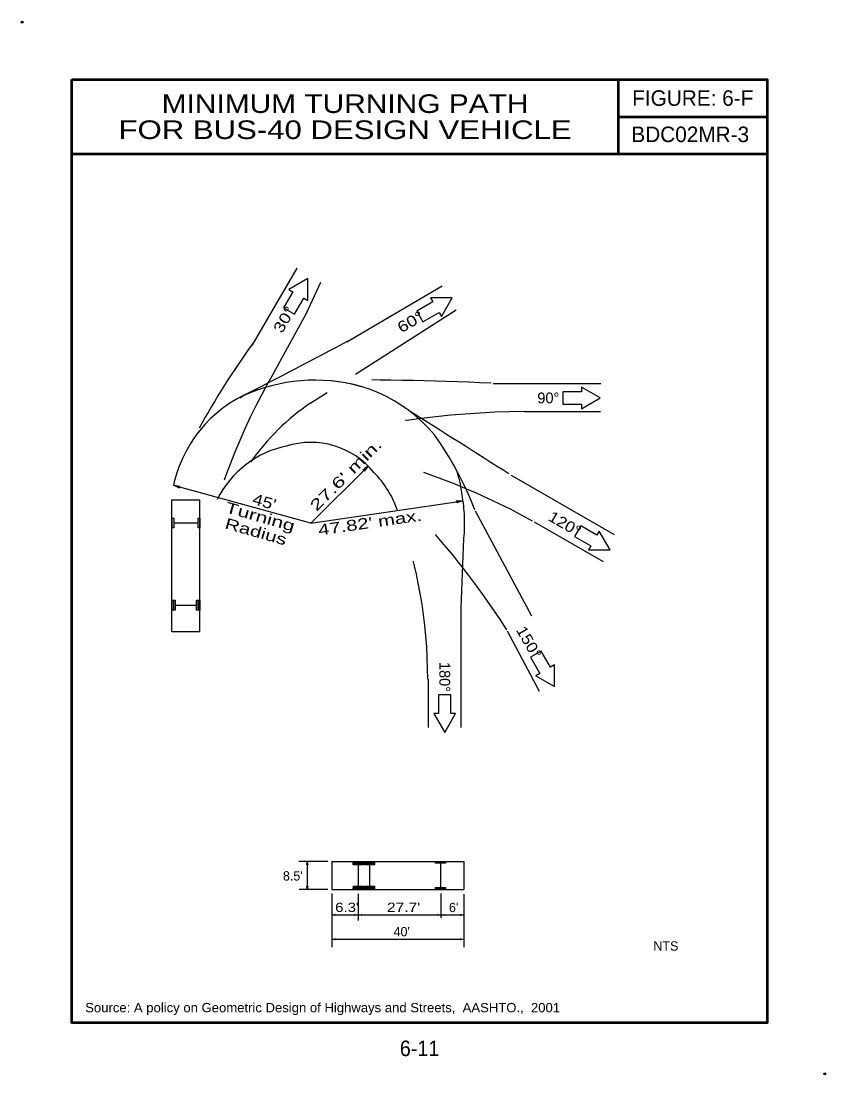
# Model space of a CAD drawing. Extents: x -3.354 to -2.679, y 4.889 to 5.773.
import ezdxf
from ezdxf.enums import TextEntityAlignment as Align

# ---------------------------------------------------------------- set-up
doc = ezdxf.new("R2010")
doc.units = 0
doc.header["$LTSCALE"] = 0.0036
doc.header["$PDMODE"] = 32
doc.header["$PDSIZE"] = 0.0018
doc.linetypes.add('LONG_DASHED', pattern=[7.5, 6, -1.5])
doc.layers.add('1', color=7, linetype='Continuous', lineweight=25)
doc.layers.add('2', color=7, linetype='Continuous', lineweight=25)

msp = doc.modelspace()

# ---------------------------------------------------------------- linework, layer by layer
at = {"layer": '1', "lineweight": 53}
for p, q in [((-2.852792, 5.724317), (-2.852792, 5.661817)), ((-2.852792, 5.693067), (-2.727792, 5.693067)), ((-3.311125, 5.661817), (-2.727792, 5.661817))]:
    msp.add_line(p, q, dxfattribs=at)
at = {"layer": '1', "linetype": 'LONG_DASHED'}
for p, q in [((-3.122458, 5.565817), (-3.160292, 5.5011)), ((-3.114492, 5.52755), (-3.102158, 5.554092)), ((-3.000542, 5.550883), (-3.080517, 5.50395)), ((-3.141508, 5.478675), (-3.114492, 5.52755)), ((-2.988808, 5.530575), (-3.097083, 5.461608)), ((-2.957633, 5.469242), (-2.867375, 5.469242)), ((-3.110725, 5.452825), (-3.097083, 5.461608)), ((-2.931367, 5.445808), (-2.867717, 5.445808)), ((-2.9427, 5.392342), (-2.854583, 5.341467)), ((-2.972808, 5.3623), (-2.897033, 5.220383)), ((-2.923267, 5.353217), (-2.865508, 5.319867)), ((-2.984625, 5.280817), (-2.98225, 5.339233)), ((-2.946117, 5.261742), (-2.919017, 5.211017))]:
    msp.add_line(p, q, dxfattribs=at)
at = {"layer": '1'}
for p, q in [((-3.062717, 5.399942), (-3.065917, 5.395575)), ((-3.225875, 5.383808), (-3.220533, 5.382908)), ((-2.983117, 5.370633), (-2.988292, 5.369033)), ((-3.225725, 5.35215), (-3.205225, 5.35215)), ((-3.22435, 5.283142), (-3.206592, 5.283142)), ((-3.09645, 5.068067), (-3.120625, 5.068067)), ((-3.11375, 5.068017), (-3.11375, 5.044675)), ((-3.113717, 5.068025), (-3.113325, 5.06535)), ((-3.070883, 5.065258), (-3.070883, 5.047492)), ((-3.061417, 5.065258), (-3.061417, 5.047492)), ((-3.001875, 5.066633), (-3.001875, 5.046133)), ((-3.09645, 5.044633), (-3.120517, 5.044633)), ((-3.113742, 5.044633), (-3.114133, 5.047308)), ((-3.093017, 5.041133), (-3.093017, 4.996242)), ((-3.070917, 5.041008), (-3.070917, 5.018617)), ((-3.001558, 5.041258), (-3.001558, 5.020933)), ((-2.982342, 5.040767), (-2.982342, 4.996242)), ((-3.092967, 5.023317), (-3.090292, 5.023717)), ((-3.092883, 5.023325), (-2.982433, 5.023325)), ((-3.071008, 5.023308), (-3.073683, 5.022908)), ((-3.070783, 5.02335), (-3.0681, 5.023742)), ((-3.001542, 5.023308), (-3.004217, 5.022908)), ((-3.001433, 5.02335), (-2.998758, 5.023742)), ((-2.982425, 5.023275), (-2.9851, 5.022883)), ((-3.093033, 5.002808), (-3.09035, 5.0032)), ((-3.093008, 5.002858), (-2.982308, 5.002858)), ((-2.982417, 5.002867), (-2.985092, 5.002475))]:
    msp.add_line(p, q, dxfattribs=at)
at = {"layer": '1', "lineweight": 53}
msp.add_lwpolyline([(-3.311125, 5.724317), (-2.727792, 5.724317), (-2.727792, 4.93265), (-3.311125, 4.93265)], close=True, dxfattribs=at)
at = {"layer": '1'}
for points in [[(-3.133492, 5.532575), (-3.124467, 5.527367), (-3.116658, 5.5409), (-3.113283, 5.538942), (-3.113267, 5.557183), (-3.129075, 5.548067), (-3.125675, 5.546108)], [(-3.02185, 5.529992), (-3.016642, 5.520975), (-3.003117, 5.528783), (-3.001167, 5.5254), (-2.992042, 5.541192), (-3.010283, 5.541192), (-3.008325, 5.537808)], [(-2.899267, 5.462275), (-2.899267, 5.451858), (-2.883642, 5.451858), (-2.883642, 5.44795), (-2.86785, 5.457067), (-2.883642, 5.466183), (-2.883642, 5.462275)], [(-3.227125, 5.347967), (-3.227125, 5.3563), (-3.225725, 5.3563), (-3.225725, 5.347967)], [(-3.205225, 5.347967), (-3.205225, 5.3563), (-3.203833, 5.3563), (-3.203833, 5.347967)], [(-2.8842, 5.349808), (-2.889408, 5.340783), (-2.875875, 5.332975), (-2.877833, 5.3296), (-2.859592, 5.329592), (-2.868708, 5.345392), (-2.870667, 5.341992)], [(-3.227158, 5.278975), (-3.227158, 5.287308), (-3.225758, 5.287308), (-3.225758, 5.278975)], [(-3.22575, 5.278975), (-3.22575, 5.287308), (-3.22435, 5.287308), (-3.22435, 5.278975)], [(-3.206592, 5.279008), (-3.206592, 5.287342), (-3.2052, 5.287342), (-3.2052, 5.279008)], [(-3.205167, 5.278975), (-3.205167, 5.287308), (-3.203767, 5.287308), (-3.203767, 5.278975)], [(-2.91735, 5.244658), (-2.926375, 5.23945), (-2.918558, 5.225925), (-2.92195, 5.223975), (-2.906158, 5.21485), (-2.906158, 5.233092), (-2.909542, 5.231133)], [(-2.993133, 5.207858), (-3.00355, 5.207858), (-3.00355, 5.192233), (-3.007458, 5.192233), (-2.998342, 5.176442), (-2.989225, 5.192233), (-2.993133, 5.192233)], [(-3.07505, 5.068058), (-3.066717, 5.068058), (-3.066717, 5.066658), (-3.07505, 5.066658)], [(-3.065583, 5.068058), (-3.05725, 5.068058), (-3.05725, 5.066658), (-3.065583, 5.066658)], [(-3.006058, 5.068025), (-2.997725, 5.068025), (-2.997725, 5.066633), (-3.006058, 5.066633)], [(-3.07505, 5.06665), (-3.066717, 5.06665), (-3.066717, 5.065258), (-3.07505, 5.065258)], [(-3.065583, 5.06665), (-3.05725, 5.06665), (-3.05725, 5.065258), (-3.065583, 5.065258)], [(-3.07505, 5.046067), (-3.066717, 5.046067), (-3.066717, 5.044675), (-3.07505, 5.044675)], [(-3.075017, 5.047492), (-3.066683, 5.047492), (-3.066683, 5.0461), (-3.075017, 5.0461)], [(-3.065583, 5.046067), (-3.05725, 5.046067), (-3.05725, 5.044675), (-3.065583, 5.044675)], [(-3.06555, 5.047492), (-3.057217, 5.047492), (-3.057217, 5.0461), (-3.06555, 5.0461)], [(-3.006058, 5.046133), (-2.997725, 5.046133), (-2.997725, 5.044733), (-3.006058, 5.044733)]]:
    msp.add_lwpolyline(points, close=True, dxfattribs=at)
for points in [[(-3.065833, 5.396775), (-3.067183, 5.396642), (-3.062667, 5.399983)], [(-3.065933, 5.395592), (-3.065825, 5.396758), (-3.065833, 5.396775)], [(-3.221642, 5.382442), (-3.220917, 5.3813), (-3.225933, 5.383842)], [(-3.220542, 5.382883), (-3.221633, 5.382467), (-3.221642, 5.382442)], [(-3.227167, 5.261008), (-3.227167, 5.371683), (-3.203725, 5.371683)], [(-3.227167, 5.261008), (-3.203725, 5.261008), (-3.203725, 5.371683)], [(-2.987508, 5.36995), (-2.988667, 5.37065), (-2.98305, 5.370633)], [(-2.9883, 5.369058), (-2.987508, 5.369933), (-2.987508, 5.36995)], [(-3.113708, 5.0658), (-3.114142, 5.065275), (-3.113708, 5.068058)], [(-3.093017, 5.068067), (-2.982342, 5.068067), (-2.982342, 5.044633)], [(-3.093017, 5.068067), (-3.093017, 5.044633), (-2.982342, 5.044633)], [(-3.113333, 5.065342), (-3.1137, 5.0658), (-3.113708, 5.0658)], [(-3.114125, 5.047317), (-3.11375, 5.046858), (-3.113742, 5.046858)], [(-3.113742, 5.046858), (-3.113308, 5.047383), (-3.113742, 5.0446)], [(-3.090742, 5.023317), (-3.090217, 5.022892), (-3.093, 5.023317)], [(-3.090283, 5.0237), (-3.090742, 5.023325), (-3.090742, 5.023317)], [(-3.073242, 5.023308), (-3.073758, 5.023733), (-3.070975, 5.023308)], [(-3.0737, 5.022925), (-3.073242, 5.0233), (-3.073242, 5.023308)], [(-3.06855, 5.02335), (-3.068033, 5.022925), (-3.070808, 5.02335)], [(-3.068092, 5.023733), (-3.06855, 5.023358), (-3.06855, 5.02335)], [(-3.003767, 5.023308), (-3.004292, 5.023733), (-3.001508, 5.023308)], [(-3.004225, 5.022925), (-3.003767, 5.0233), (-3.003767, 5.023308)], [(-2.999208, 5.02335), (-2.998683, 5.022925), (-3.001467, 5.02335)], [(-2.99875, 5.023733), (-2.999208, 5.023358), (-2.999208, 5.02335)], [(-2.984658, 5.023275), (-2.985175, 5.0237), (-2.982392, 5.023275)], [(-2.985117, 5.022892), (-2.984658, 5.023267), (-2.984658, 5.023275)], [(-3.0908, 5.002808), (-3.090283, 5.002383), (-3.093058, 5.002808)], [(-3.090342, 5.003192), (-3.0908, 5.002817), (-3.0908, 5.002808)], [(-2.984642, 5.002867), (-2.985167, 5.0033), (-2.982383, 5.002867)], [(-2.9851, 5.002483), (-2.984642, 5.002858), (-2.984642, 5.002867)]]:
    msp.add_lwpolyline(points, dxfattribs=at)
at = {"layer": '1', "linetype": 'LONG_DASHED'}
for centre, radius, start, end in [((-2.649658, 5.129911), 0.631436, 143.85184, 151.45564), ((-5.215751, 9.492155), 4.523442, 296.91573, 298.19355), ((-2.655719, 5.198735), 0.560674, 150.04704, 167.5392), ((-3.107381, 5.327415), 0.144521, 74.65813, 114.57173), ((-3.10463, 5.344889), 0.127001, 39.79656, 93.02916), ((-3.095024, 2.321509), 3.150838, 87.53498, 90.25069), ((-3.117009, 5.359497), 0.111714, 116.17598, 173.14712), ((-3.089515, 5.339567), 0.142368, 123.0881, 124.50135), ((-3.00189, 5.291288), 0.194783, 123.97021, 144.80772), ((-2.927021, 4.721892), 0.7237, 90.36182, 106.05387), ((-12.138996, -9.051551), 17.122876, 57.52224, 57.8535), ((-3.232552, 5.264489), 0.277481, 20.82313, 35.6417), ((-3.114562, 5.335272), 0.08304, 100.81496, 153.94695), ((-3.11056, 5.352056), 0.067706, 38.8501, 107.85479), ((-3.207841, 4.84031), 0.586398, 61.12327, 77.53681), ((-3.11056, 5.352056), 0.067706, 126.80984, 126.85263), ((-3.527567, 4.88833), 0.69141, 32.76059, 47.53614), ((-3.117956, 5.335002), 0.084604, 18.94696, 44.71164), ((-3.085948, 5.364389), 0.102734, 6.28138, 17.97188), ((-3.11056, 5.352056), 0.128908, 354.39784, 10.53749), ((-3.417047, 5.221971), 0.404411, 359.8542, 20.34184)]:
    msp.add_arc(centre, radius, start, end, dxfattribs=at)
at = {"layer": '1'}
for p in [(-3.352842, 5.772392), (-2.679508, 4.889892)]:
    msp.add_point(p, dxfattribs=at)
at = {"layer": '2'}
for q in [(-3.062683, 5.399933), (-3.223592, 5.382975), (-2.983, 5.370617)]:
    msp.add_line((-3.110558, 5.352058), q, dxfattribs=at)
at = {"layer": '2', "linetype": 'LONG_DASHED'}
for p, q in [((-2.984625, 5.180658), (-2.984625, 5.280817)), ((-3.011925, 5.180658), (-3.011925, 5.22095))]:
    msp.add_line(p, q, dxfattribs=at)

# ---------------------------------------------------------------- texts
at = {"layer": '1'}
for s, height, p in [('FIGURE: 6-F', 0.01303, (-2.790296, 5.702175)), ('BDC02MR-3', 0.01303, (-2.792429, 5.671733)), ("8.5'", 0.007817, (-3.125821, 5.0521)), ("6'", 0.007817, (-2.990921, 5.025617)), ("40'", 0.007817, (-3.034442, 5.005317)), ('NTS', 0.007817, (-2.812838, 4.9933))]:
    msp.add_text(s, height=height, dxfattribs=at).set_placement(p, align=Align.CENTER)
for s, height, width, p in [('MINIMUM TURNING PATH', 0.01562, 1.2, (-3.081962, 5.696192)), ('FOR BUS-40 DESIGN VEHICLE', 0.01562, 1.25, (-3.081958, 5.674317)), ("6.3'", 0.007817, 1.2, (-3.08035, 5.025683)), ("27.7'", 0.007817, 1.25, (-3.032871, 5.02575)), ('6-11', 0.01303, 0.95, (-3.019458, 4.904758))]:
    msp.add_text(s, height=height, dxfattribs=dict(at, width=width)).set_placement(p, align=Align.CENTER)
for s, rotation, width, p in [('30°', 60, 1.25, (-3.123363, 5.530587)), ('60°', 30, 1.25, (-3.014796, 5.522791)), ('120°', 330, 1.15, (-2.887296, 5.340314)), ('150°', 300, 1.15, (-2.924364, 5.237271))]:
    msp.add_text(s, height=0.009108, rotation=rotation, dxfattribs=dict(at, width=width)).set_placement(p, align=Align.RIGHT)
msp.add_text('90°', height=0.009108, dxfattribs=at).set_placement((-2.90225, 5.452508), align=Align.RIGHT)
for s, rotation, width, p in [("27.6' min.", 45, 1.5, (-3.078119, 5.389214)), ('Turning', 344.112, 1.45, (-3.154431, 5.353057)), ("45'", 344.112, 1.25, (-3.15086, 5.36558)), ("47.82' max.", 8.279, 1.4, (-3.060465, 5.347897)), ('Radius', 344.112, 1.4, (-3.157998, 5.340528))]:
    msp.add_text(s, height=0.009117, rotation=rotation, dxfattribs=dict(at, width=width)).set_placement(p, align=Align.CENTER)
msp.add_text('180°', height=0.009108, rotation=270, dxfattribs=at).set_placement((-3.0029, 5.210292), align=Align.RIGHT)
at = {"layer": '1', "width": 1.05}
msp.add_text('Source: A policy on Geometric Design of Highways and Streets,  AASHTO.,  2001', height=0.007817, dxfattribs=at).set_placement((-3.299967, 4.941567))

doc.saveas('drawing.dxf')
